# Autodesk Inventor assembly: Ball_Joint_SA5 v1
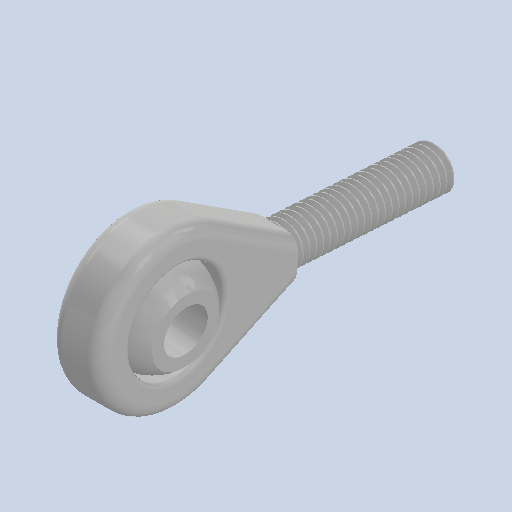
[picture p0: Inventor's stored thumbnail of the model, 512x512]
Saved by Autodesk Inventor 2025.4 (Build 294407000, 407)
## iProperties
Created: 2026-09
Part Number: Ball_Joint_SA5 v1
Document SubType Name: Assembly
Designer: AdminForWorker
Title: rotula v1
Author: AdminForWorker
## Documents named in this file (3)
- c:\worker\convert-fusion-r05-cosv3\tmp\job-1\19\temp\files\ca3d996b-dda0-445d-8bee-12a194174ca8\rotula v1_2.iam
- c:\worker\convert-fusion-r05-cosv3\tmp\job-1\19\temp\files\ca3d996b-dda0-445d-8bee-12a194174ca8\Component33.ipt
- c:\worker\convert-fusion-r05-cosv3\tmp\job-1\19\temp\files\ca3d996b-dda0-445d-8bee-12a194174ca8\Component34.ipt
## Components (2 placed, 2 different names)
1. Component33:1
2. Component34:1
